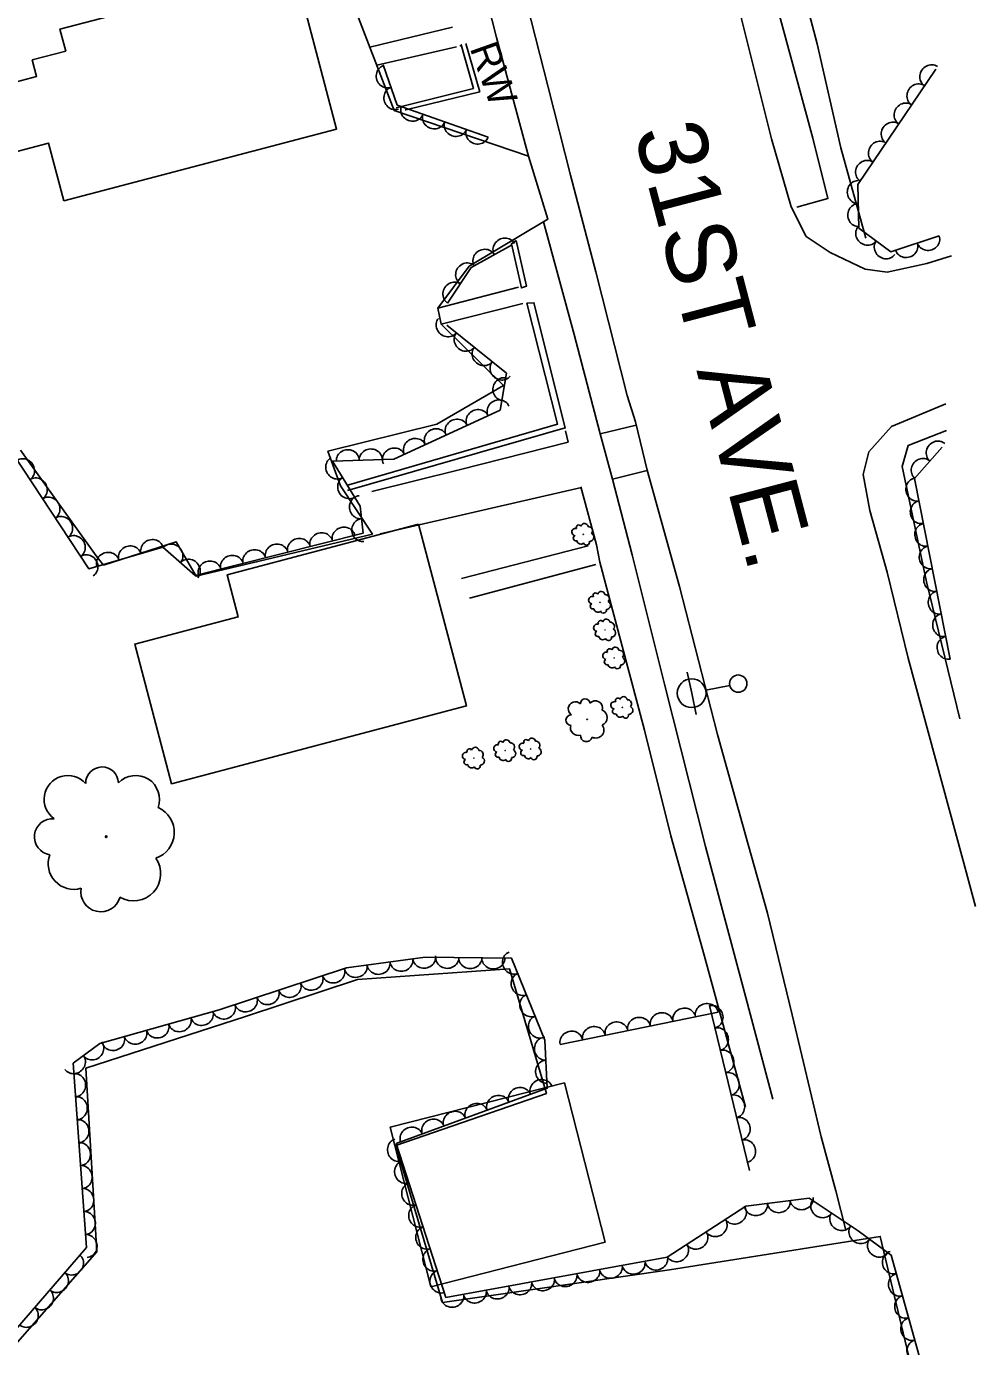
# Model space of a CAD drawing. Extents: x 1722896 to 1754269, y 648279 to 666297.
# Drawn here: x 1725961.7 to 1726126.5, y 664101 to 664330.2 of the extents above; entities that cross this region are included whole.
import ezdxf

# ---------------------------------------------------------------- set-up
doc = ezdxf.new("R2010")
doc.units = 0
for name, color, linetype in [('DESIGN - CENTERLINE - Proposed Text', 7, 'Continuous'), ('DESIGN - SHEET - Linework', 7, 'Continuous'), ('SURVEY - CENTERLINE - Preliminary', 7, 'Continuous'), ('SURVEY - CENTERLINE - Preliminary Text', 7, 'Continuous'), ('SURVEY - CONTROL with Text', 7, 'Continuous'), ('SURVEY - DTM - Breaklines', 7, 'Continuous'), ('SURVEY - VEGETATION - Features with Text', 7, 'Continuous')]:
    doc.layers.add(name, color=color, linetype=linetype)

msp = doc.modelspace()

# ---------------------------------------------------------------- linework, layer by layer
at = {"layer": 'DESIGN - CENTERLINE - Proposed Text'}
for points in [[(1725968.15, 664299.92), (1726015.51, 664312.37), (1726008.14, 664340.42), (1725967.49, 664329.74), (1725968.5, 664325.93), (1725962.67, 664324.4), (1725963.42, 664321.54), (1725956.39, 664319.69), (1725959.37, 664308.35), (1725965.51, 664309.96)], [(1726029.74, 664243.77), (1726038.06, 664212.22), (1725986.87, 664198.72), (1725980.48, 664222.96), (1725998.44, 664227.69), (1725996.51, 664235)], [(1726055.09, 664146.79), (1726062.15, 664119.09), (1726031.9, 664111.38), (1726024.84, 664139.09)]]:
    msp.add_lwpolyline(points, close=True, dxfattribs=at)
for points in [[(1726021.29, 664326.65), (1726035.62, 664330.07)], [(1726022.49, 664323.51), (1726036.34, 664326.69)], [(1726025.87, 664316.11), (1726039.29, 664319.44), (1726037.16, 664327.04), (1726036.91, 664326.79)], [(1726027.53, 664315.75), (1726040.37, 664318.86), (1726037.97, 664327.28)], [(1726027.44, 664315.73), (1726027.53, 664315.75)], [(1726046.73, 664293.04), (1726048.52, 664285.14), (1726047.6, 664284.81), (1726045.89, 664292.5), (1726046.73, 664293.04)], [(1726033.12, 664281.29), (1726047.09, 664284.96)], [(1726017.41, 664249.65), (1726055.23, 664260.5), (1726049.79, 664282.23), (1726048.57, 664282.15), (1726053.86, 664261.13), (1726017.25, 664250.48)], [(1726033.7, 664278.5), (1726047.86, 664282.09)], [(1726037.23, 664234.35), (1726059.21, 664240.01)], [(1726038.58, 664230.94), (1726060.51, 664236.79)]]:
    msp.add_lwpolyline(points, dxfattribs=at)
at = {"layer": 'SURVEY - CENTERLINE - Preliminary'}
for points in [[(1726017.88, 664335.55), (1726025.52, 664315.62), (1726048.85, 664307.71), (1726052.18, 664296.74), (1726038.57, 664288.62), (1726033.12, 664281.29), (1726033.7, 664278.5), (1726044.48, 664267.86), (1726032.91, 664261.14), (1726014.03, 664256.44), (1726016.19, 664250.47), (1726021.75, 664242.08), (1725991.12, 664234.76), (1725987.68, 664240.74), (1725975.07, 664236.68), (1725973.8, 664238.32), (1725960.62, 664256.66)], [(1725955.02, 664175.91), (1725942.43, 664155.15), (1725940.35, 664125.84), (1725950.62, 664101.84), (1725960.1, 664101.74), (1725973.89, 664117.44), (1725972.01, 664149.33), (1725999.72, 664158.3), (1726019.16, 664164.7), (1726045.54, 664166.58), (1726051.94, 664144.95), (1726025.8, 664135.92), (1726033.91, 664108.65), (1726073.35, 664114.29), (1726109.92, 664120.12), (1726118.23, 664085.17)]]:
    msp.add_lwpolyline(points, dxfattribs=at)
at = {"layer": 'SURVEY - CENTERLINE - Preliminary Text'}
for points in [[(1726054.55, 664452.02), (1726059.92, 664430.01), (1726063.68, 664416.85), (1726069.27, 664395.77), (1726074.98, 664373.29), (1726081.19, 664349.65), (1726085.72, 664332.02), (1726091.06, 664310.73), (1726094.47, 664298.9), (1726097.03, 664293.76), (1726101.24, 664290.95), (1726107.31, 664288.05), (1726111.1, 664287.57), (1726118.02, 664289.03), (1726122.29, 664290.41)], [(1726029.35, 664408.54), (1726033.35, 664392.59), (1726039.3, 664369.99), (1726047.86, 664336.97), (1726052.23, 664319.67), (1726056.15, 664304.39), (1726060.55, 664287.58), (1726065.98, 664266.15), (1726067.4, 664261.57), (1726069.43, 664253.18), (1726075.06, 664232.95), (1726081.66, 664207.25), (1726087.01, 664188.19), (1726090.33, 664176.23), (1726094.63, 664158.58), (1726099.65, 664137.39), (1726102.18, 664128.01), (1726103.96, 664121.22)], [(1726026.08, 664394.8), (1726031.02, 664376.89), (1726035.88, 664357.4), (1726043.26, 664328.28), (1726048.85, 664307.71)], [(1726085.78, 664379.82), (1726092.88, 664350.28), (1726098.96, 664327.22), (1726103.1, 664309.13), (1726107.43, 664293.43)], [(1726081.11, 664377.47), (1726090.21, 664340.28), (1726098.22, 664310.83), (1726100.83, 664300.33), (1726095.42, 664298.86)], [(1726051.44, 664296.3), (1726056.8, 664276.72), (1726061.28, 664259.47), (1726063.43, 664251.63), (1726066.83, 664238.47), (1726072.45, 664216.03), (1726079.58, 664187.82), (1726086.56, 664161.62), (1726091.26, 664143.94)], [(1726121.3, 664264.66), (1726111.88, 664260.76), (1726107.94, 664256.33), (1726106.96, 664252.41), (1726108.11, 664246.15), (1726111.13, 664235.43), (1726114.78, 664220.53), (1726124.25, 664185.55), (1726126.47, 664177.39)], [(1726055.71, 664258.05), (1726055.27, 664260.02)], [(1726067.54, 664261), (1726061.26, 664259.47)], [(1726121.41, 664260.04), (1726114.76, 664257.48), (1726113.74, 664253.82), (1726117.97, 664233.76), (1726123.73, 664209.99)], [(1726055.71, 664258.05), (1726036.78, 664253.23), (1726021.65, 664249.44)], [(1726069.45, 664253.1), (1726063.43, 664251.63)], [(1726057.91, 664250.27), (1726060.64, 664240.18), (1726061.2, 664237.21), (1726068.98, 664208.01), (1726073.58, 664189.65), (1726079.33, 664168.97), (1726086.53, 664142.59)], [(1726058.04, 664250.16), (1726042.43, 664246.58), (1726023.08, 664242.09)]]:
    msp.add_lwpolyline(points, dxfattribs=at)
at = {"layer": 'SURVEY - DTM - Breaklines'}
for p, q in [((1726077.18, 664214.44), (1726076.42, 664218.11)), ((1726077.18, 664214.44), (1726077.94, 664210.76)), ((1726083.79, 664215.8), (1726079.63, 664214.94))]:
    msp.add_line(p, q, dxfattribs=at)
for centre, radius in [((1726077.18, 664214.44), 2.5), ((1726085.26, 664216.1), 1.5)]:
    msp.add_circle(centre, radius, dxfattribs=at)
at = {"layer": 'SURVEY - VEGETATION - Features with Text'}
for points in [[(1726041.85, 664311.02), (1726026.06, 664316.56), (1726023.61, 664323.53)], [(1726120.17, 664293.84), (1726111.78, 664291.1), (1726106.22, 664295.2), (1726106.05, 664302.77), (1726119.54, 664322.83)], [(1725958.99, 664302.53), (1725940.25, 664293.13), (1725939.26, 664279.9), (1725945.59, 664275.74), (1725951.13, 664262.39), (1725959.4, 664255.89), (1725972.48, 664236.05), (1725985.35, 664239.77), (1725990.94, 664234.86), (1726020.11, 664242.23), (1726019.62, 664246.93), (1726014.84, 664254.76), (1726025.45, 664255.1), (1726043.9, 664263.59), (1726045.05, 664269.99), (1726034.64, 664278.35)], [(1726034.8, 664282.18), (1726038.87, 664288.34), (1726045.91, 664292.26)], [(1726122.06, 664220.37), (1726115.87, 664251.7), (1726120.64, 664257.19)], [(1726117.23, 664097.31), (1726111.83, 664116.86), (1726106.07, 664121.06), (1726097.57, 664126.78), (1726086.58, 664125.38), (1726072.94, 664116.51), (1726034.51, 664109.51), (1726025.88, 664136.23), (1726052.11, 664145.83), (1726051.68, 664154.17), (1726045.92, 664168.4), (1726030.88, 664168.59), (1726017.22, 664166.75), (1725995.13, 664159.47), (1725974.4, 664153.62), (1725969.8, 664150.18), (1725972.08, 664118.16), (1725959.42, 664103.51)], [(1726054.32, 664153.46), (1726081.8, 664159.08)], [(1726080.26, 664160.19), (1726087.2, 664131.54)]]:
    msp.add_lwpolyline(points, dxfattribs=at)
for centre, radius in [((1726058.35, 664242.03), 0.022), ((1726061.27, 664230.22), 0.022), ((1726062.15, 664225.44), 0.022), ((1726063.72, 664220.56), 0.022), ((1726065.13, 664211.97), 0.022), ((1726059.03, 664209.89), 0.0428), ((1726044.8, 664204.47), 0.022), ((1726049.22, 664204.76), 0.022), ((1726039.37, 664203.17), 0.022), ((1725975.52, 664189.52), 0.145)]:
    msp.add_circle(centre, radius, dxfattribs=at)
for centre, radius, start, end in [((1726057.57, 664243.22), 0.433, 30.3727, 209.1184), ((1726058.56, 664243.28), 0.631, 8.2566, 165.0455), ((1726059.24, 664242.65), 0.719, 317.3093, 94.8335), ((1726056.99, 664242.42), 0.629, 70.3934, 263.8131), ((1726057.1, 664241.35), 0.479, 113.0121, 290.3312), ((1726059.46, 664241.52), 0.714, 268.2051, 64.0436), ((1726057.94, 664241), 0.679, 188.2991, 315.1448), ((1726058.92, 664240.69), 0.527, 198.458, 13.4583), ((1726061.48, 664231.47), 0.631, 8.2566, 165.0455), ((1726059.91, 664230.61), 0.629, 70.3934, 263.8131), ((1726060.03, 664229.54), 0.479, 113.0121, 290.3312), ((1726060.5, 664231.41), 0.433, 30.3727, 209.1184), ((1726062.17, 664230.84), 0.719, 317.3093, 94.8335), ((1726062.38, 664229.71), 0.714, 268.2051, 64.0436), ((1726060.87, 664229.19), 0.679, 188.2991, 315.1448), ((1726061.85, 664228.88), 0.527, 198.458, 13.4583), ((1726062.36, 664226.68), 0.631, 8.2566, 165.0455), ((1726060.78, 664225.82), 0.629, 70.3934, 263.8131), ((1726060.9, 664224.76), 0.479, 113.0121, 290.3312), ((1726061.37, 664226.63), 0.433, 30.3727, 209.1184), ((1726063.04, 664226.06), 0.719, 317.3093, 94.8335), ((1726063.26, 664224.93), 0.714, 268.2051, 64.0436), ((1726061.74, 664224.41), 0.679, 188.2991, 315.1448), ((1726062.72, 664224.09), 0.527, 198.458, 13.4583), ((1726062.35, 664220.94), 0.629, 70.3934, 263.8131), ((1726062.94, 664221.74), 0.433, 30.3727, 209.1184), ((1726063.93, 664221.8), 0.631, 8.2566, 165.0455), ((1726064.61, 664221.18), 0.719, 317.3093, 94.8335), ((1726064.83, 664220.05), 0.714, 268.2051, 64.0436), ((1726062.47, 664219.87), 0.479, 113.0121, 290.3312), ((1726063.31, 664219.52), 0.679, 188.2991, 315.1448), ((1726064.29, 664219.21), 0.527, 198.458, 13.4583), ((1726064.36, 664213.16), 0.433, 30.3727, 209.1184), ((1726065.34, 664213.21), 0.631, 8.2566, 165.0455), ((1726056.98, 664211.72), 1.23, 44.3141, 237.7338), ((1726058.7, 664212.62), 0.843, 4.2934, 183.0391), ((1726060.46, 664211.88), 1.23, 342.1773, 138.9662), ((1726061.13, 664210.2), 1.4, 291.23, 68.7542), ((1726063.77, 664212.35), 0.629, 70.3934, 263.8131), ((1726063.89, 664211.29), 0.479, 113.0121, 290.3312), ((1726066.03, 664212.59), 0.719, 317.3093, 94.8335), ((1726066.24, 664211.46), 0.714, 268.2051, 64.0436), ((1726056.27, 664209.76), 0.932, 86.9328, 264.2519), ((1726064.73, 664210.94), 0.679, 188.2991, 315.1448), ((1726065.71, 664210.62), 0.527, 198.458, 13.4583), ((1726057.44, 664208.42), 1.32, 162.2198, 289.0655), ((1726058.89, 664207.04), 1.02, 172.3787, 347.379), ((1726060.54, 664208.04), 1.39, 242.1258, 37.9643), ((1726038.59, 664204.35), 0.433, 30.3727, 209.1184), ((1726039.58, 664204.41), 0.631, 8.2566, 165.0455), ((1726040.26, 664203.79), 0.719, 317.3093, 94.8335), ((1726043.44, 664204.85), 0.629, 70.3934, 263.8131), ((1726044.03, 664205.66), 0.433, 30.3727, 209.1184), ((1726045.01, 664205.71), 0.631, 8.2566, 165.0455), ((1726045.7, 664205.09), 0.719, 317.3093, 94.8335), ((1726045.91, 664203.96), 0.714, 268.2051, 64.0436), ((1726047.86, 664205.14), 0.629, 70.3934, 263.8131), ((1726047.98, 664204.08), 0.479, 113.0121, 290.3312), ((1726048.45, 664205.95), 0.433, 30.3727, 209.1184), ((1726049.43, 664206), 0.631, 8.2566, 165.0455), ((1726050.12, 664205.38), 0.719, 317.3093, 94.8335), ((1726050.33, 664204.25), 0.714, 268.2051, 64.0436), ((1726038, 664203.55), 0.629, 70.3934, 263.8131), ((1726038.12, 664202.48), 0.479, 113.0121, 290.3312), ((1726040.48, 664202.66), 0.714, 268.2051, 64.0436), ((1726043.56, 664203.79), 0.479, 113.0121, 290.3312), ((1726044.4, 664203.43), 0.679, 188.2991, 315.1448), ((1726045.38, 664203.12), 0.527, 198.458, 13.4583), ((1726048.82, 664203.73), 0.679, 188.2991, 315.1448), ((1726049.8, 664203.41), 0.527, 198.458, 13.4583), ((1725968.87, 664196.02), 4.13, 41.672, 235.0917), ((1725974.8, 664198.79), 2.84, 1.6513, 180.3969), ((1725980.64, 664196.01), 4.14, 339.5351, 136.3241), ((1726038.96, 664202.13), 0.679, 188.2991, 315.1448), ((1726039.94, 664201.82), 0.527, 198.458, 13.4583), ((1725982.62, 664190.26), 4.72, 288.5879, 66.1121), ((1725966.2, 664189.5), 3.15, 84.2907, 261.6098), ((1725969.91, 664184.84), 4.46, 159.5777, 286.4234), ((1725980.29, 664183.07), 4.69, 239.4837, 35.3222), ((1725974.58, 664179.94), 3.46, 169.7366, 344.7369)]:
    msp.add_arc(centre, radius, start, end, dxfattribs=at)
for centre, major_axis in [((1726118.71, 664321.6), (1.12, 1.66)), ((1726024.31, 664321.53), (-0.66, 1.89)), ((1726025.64, 664317.76), (-0.66, 1.89)), ((1726116.48, 664318.28), (1.12, 1.66)), ((1726114.25, 664314.96), (1.12, 1.66)), ((1726028.64, 664315.66), (-1.89, 0.66)), ((1726032.41, 664314.33), (-1.89, 0.66)), ((1726036.19, 664313.01), (-1.89, 0.66)), ((1726039.96, 664311.68), (-1.89, 0.66)), ((1726112.01, 664311.64), (1.12, 1.66)), ((1726109.78, 664308.32), (1.12, 1.66)), ((1726107.55, 664305), (1.12, 1.66)), ((1726106.08, 664301.46), (-0.05, 2)), ((1726106.17, 664297.46), (-0.05, 2)), ((1726107.62, 664294.17), (-1.61, 1.19)), ((1726118.27, 664293.22), (-1.9, -0.62)), ((1726041.16, 664289.61), (1.75, 0.97)), ((1726044.65, 664291.56), (1.75, 0.97)), ((1726110.84, 664291.8), (-1.61, 1.19)), ((1726114.47, 664291.98), (-1.9, -0.62)), ((1726038.11, 664287.19), (1.1, 1.67)), ((1726035.9, 664283.85), (1.1, 1.67)), ((1726034.76, 664278.26), (-1.56, 1.25)), ((1726037.88, 664275.75), (-1.56, 1.25)), ((1726041, 664273.25), (-1.56, 1.25)), ((1726044.12, 664270.74), (-1.56, 1.25)), ((1726044.55, 664267.23), (0.35, 1.97)), ((1726043.63, 664263.46), (1.82, 0.84)), ((1726036.36, 664260.12), (1.82, 0.84)), ((1726040, 664261.79), (1.82, 0.84)), ((1726032.73, 664258.45), (1.82, 0.84)), ((1726025.46, 664255.1), (1.82, 0.84)), ((1726029.1, 664256.77), (1.82, 0.84)), ((1726119.84, 664256.28), (1.31, 1.51)), ((1725961.17, 664253.2), (1.1, -1.67)), ((1726015.55, 664253.59), (-1.04, 1.71)), ((1726017.47, 664254.84), (2, 0.06)), ((1726021.46, 664254.97), (2, 0.06)), ((1726117.22, 664253.26), (1.31, 1.51)), ((1725963.37, 664249.86), (1.1, -1.67)), ((1726017.63, 664250.18), (-1.04, 1.71)), ((1726116.25, 664249.8), (-0.39, 1.96)), ((1725965.58, 664246.52), (1.1, -1.67)), ((1726019.64, 664246.74), (-0.21, 1.99)), ((1726117.02, 664245.87), (-0.39, 1.96)), ((1725967.78, 664243.18), (1.1, -1.67)), ((1726016.75, 664241.38), (1.94, 0.49)), ((1726020.06, 664242.76), (-0.21, 1.99)), ((1726117.8, 664241.95), (-0.39, 1.96)), ((1725969.98, 664239.84), (1.1, -1.67)), ((1725983.49, 664239.23), (1.92, 0.56)), ((1726008.99, 664239.42), (1.94, 0.49)), ((1726012.87, 664240.4), (1.94, 0.49)), ((1725975.8, 664237.01), (1.92, 0.56)), ((1725979.64, 664238.12), (1.92, 0.56)), ((1725986.9, 664238.41), (1.5, -1.32)), ((1726001.24, 664237.46), (1.94, 0.49)), ((1726005.12, 664238.44), (1.94, 0.49)), ((1726118.57, 664238.02), (-0.39, 1.96)), ((1725972.18, 664236.5), (1.1, -1.67)), ((1725989.91, 664235.77), (1.5, -1.32)), ((1725993.48, 664235.5), (1.94, 0.49)), ((1725997.36, 664236.48), (1.94, 0.49)), ((1726119.35, 664234.1), (-0.39, 1.96)), ((1726120.12, 664230.18), (-0.39, 1.96)), ((1726120.9, 664226.25), (-0.39, 1.96)), ((1726121.67, 664222.33), (-0.39, 1.96)), ((1726022.81, 664167.5), (-1.98, -0.27)), ((1726026.77, 664168.04), (-1.98, -0.27)), ((1726030.74, 664168.57), (-1.98, -0.27)), ((1726034.74, 664168.54), (-2, 0.02)), ((1726038.74, 664168.49), (-2, 0.02)), ((1726042.74, 664168.44), (-2, 0.02)), ((1726046.22, 664167.64), (-0.75, 1.85)), ((1726014.98, 664166.01), (-1.9, -0.63)), ((1726018.85, 664166.97), (-1.98, -0.27)), ((1726047.73, 664163.93), (-0.75, 1.85)), ((1726007.38, 664163.51), (-1.9, -0.63)), ((1726011.18, 664164.76), (-1.9, -0.63)), ((1725999.78, 664161), (-1.9, -0.63)), ((1726003.58, 664162.26), (-1.9, -0.63)), ((1726049.23, 664160.23), (-0.75, 1.85)), ((1725992.14, 664158.63), (-1.92, -0.54)), ((1725995.98, 664159.75), (-1.9, -0.63)), ((1726071.96, 664157.07), (1.96, 0.4)), ((1726075.88, 664157.87), (1.96, 0.4)), ((1726079.8, 664158.67), (1.96, 0.4)), ((1726080.73, 664158.24), (0.47, -1.94)), ((1725984.45, 664156.45), (-1.92, -0.54)), ((1725988.29, 664157.54), (-1.92, -0.54)), ((1726050.73, 664156.52), (-0.75, 1.85)), ((1726060.2, 664154.67), (1.96, 0.4)), ((1726064.12, 664155.47), (1.96, 0.4)), ((1726068.04, 664156.27), (1.96, 0.4)), ((1726081.67, 664154.35), (0.47, -1.94)), ((1725976.75, 664154.28), (-1.92, -0.54)), ((1725980.6, 664155.37), (-1.92, -0.54)), ((1726051.76, 664152.71), (-0.1, 2)), ((1726056.28, 664153.87), (1.96, 0.4)), ((1725973.15, 664152.68), (-1.6, -1.2)), ((1726082.62, 664150.47), (0.47, -1.94)), ((1725969.95, 664150.29), (-1.6, -1.2)), ((1726051.96, 664148.71), (-0.1, 2)), ((1725970.07, 664146.37), (0.14, -1.99)), ((1726051.07, 664145.45), (1.88, 0.69)), ((1726083.56, 664146.58), (0.47, -1.94)), ((1726043.55, 664142.7), (1.88, 0.69)), ((1726047.31, 664144.07), (1.88, 0.69)), ((1726084.5, 664142.69), (0.47, -1.94)), ((1725970.36, 664142.38), (0.14, -1.99)), ((1726039.8, 664141.32), (1.88, 0.69)), ((1725970.64, 664138.39), (0.14, -1.99)), ((1726032.28, 664138.57), (1.88, 0.69)), ((1726036.04, 664139.94), (1.88, 0.69)), ((1726085.44, 664138.8), (0.47, -1.94)), ((1726028.53, 664137.19), (1.88, 0.69)), ((1725970.92, 664134.4), (0.14, -1.99)), ((1726026.25, 664135.1), (-0.61, 1.9)), ((1726086.38, 664134.92), (0.47, -1.94)), ((1725971.21, 664130.41), (0.14, -1.99)), ((1726027.48, 664131.29), (-0.61, 1.9)), ((1726028.71, 664127.49), (-0.61, 1.9)), ((1725971.49, 664126.42), (0.14, -1.99)), ((1726096.27, 664126.62), (-1.98, -0.25)), ((1725971.77, 664122.43), (0.14, -1.99)), ((1726029.93, 664123.68), (-0.61, 1.9)), ((1726084.71, 664124.17), (-1.68, -1.09)), ((1726088.34, 664125.6), (-1.98, -0.25)), ((1726092.31, 664126.11), (-1.98, -0.25)), ((1726099.81, 664125.28), (-1.66, 1.12)), ((1726103.12, 664123.05), (-1.66, 1.12)), ((1726081.36, 664121.99), (-1.68, -1.09)), ((1726106.43, 664120.8), (-1.62, 1.18)), ((1725972.06, 664118.44), (0.14, -1.99)), ((1726031.16, 664119.87), (-0.61, 1.9)), ((1726078.01, 664119.81), (-1.68, -1.09)), ((1726109.66, 664118.44), (-1.62, 1.18)), ((1726032.39, 664116.07), (-0.61, 1.9)), ((1726074.65, 664117.63), (-1.68, -1.09)), ((1726112.18, 664115.59), (-0.53, 1.93)), ((1725969.65, 664115.35), (-1.31, -1.51)), ((1726063.14, 664114.72), (-1.97, -0.36)), ((1726067.08, 664115.44), (-1.97, -0.36)), ((1726071.01, 664116.16), (-1.97, -0.36)), ((1725967.03, 664112.32), (-1.31, -1.51)), ((1726033.62, 664112.26), (-0.61, 1.9)), ((1726051.34, 664112.57), (-1.97, -0.36)), ((1726055.27, 664113.29), (-1.97, -0.36)), ((1726059.21, 664114.01), (-1.97, -0.36)), ((1726113.24, 664111.73), (-0.53, 1.93)), ((1725964.42, 664109.29), (-1.31, -1.51)), ((1726039.53, 664110.42), (-1.97, -0.36)), ((1726043.47, 664111.14), (-1.97, -0.36)), ((1726047.4, 664111.86), (-1.97, -0.36)), ((1726035.6, 664109.7), (-1.97, -0.36)), ((1726114.31, 664107.88), (-0.53, 1.93)), ((1725961.8, 664106.27), (-1.31, -1.51)), ((1726115.38, 664104.02), (-0.53, 1.93)), ((1726116.44, 664100.17), (-0.53, 1.93))]:
    msp.add_ellipse(centre, major_axis=major_axis, ratio=0.940188, start_param=0, end_param=3.141593, dxfattribs=at)

# ---------------------------------------------------------------- texts
at = {"layer": 'DESIGN - SHEET - Linework'}
msp.add_text('31ST AVE.', height=12, rotation=284.6783, dxfattribs=at).set_placement((1726067.13, 664311.91))
at = {"layer": 'SURVEY - CONTROL with Text'}
msp.add_text('RW', height=5, rotation=289.5203, dxfattribs=at).set_placement((1726038.6, 664326.47))

doc.saveas('drawing.dxf')
